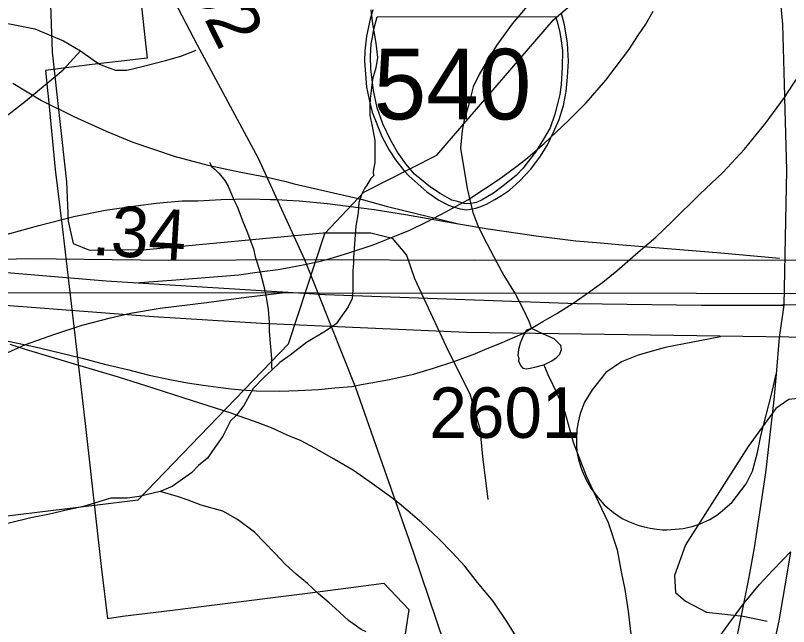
# Model space of a CAD drawing. Extents: x 2169602 to 2449496, y 721995 to 810662.
# Drawn here: x 2387770 to 2389685, y 798519 to 800033 of the extents above; entities that cross this region are included whole.
import ezdxf

# ---------------------------------------------------------------- set-up
doc = ezdxf.new("R2010")
doc.units = 0
doc.layers.add('Default', color=7, linetype='Continuous')

msp = doc.modelspace()

# ---------------------------------------------------------------- linework, layer by layer
at = {"layer": 'Default'}
for points in [[(2387480.1, 801917.5), (2387516.2, 801868.3), (2387556, 801747.9), (2387641.8, 801468.3), (2387761.6, 801071.5), (2387861, 800727), (2387914.9, 800579.3), (2388020.5, 800342.7), (2388219.9, 799960.5), (2388371.1, 799679.8), (2388485.8, 799428.9)], [(2389486.1, 801124.5), (2389522.7, 800969.7), (2389569.9, 800753.7), (2389596.1, 800625.4), (2389614.4, 800496), (2389638, 800341.5), (2389669.4, 800011.6), (2389674.7, 799833.5)], [(2388058.7, 800264.8), (2388096, 799927.2), (2387959.5, 799911.8), (2387844, 799896.7), (2387850, 799840.4), (2387850.7, 799833.2), (2387867.7, 799651.2), (2387885, 799509.9), (2387937, 799063.9), (2387943, 799014.9), (2387981.5, 798667.4), (2387997.2, 798538.9), (2388035, 798544), (2388158.5, 798559.2), (2388242.7, 798570.1), (2388499.5, 798602.2), (2388681.7, 798626.6), (2388744, 798561.1), (2388699.2, 798264.6)], [(2388058.7, 800264.8), (2388096, 799927.2), (2387959.5, 799911.8), (2387844, 799896.7), (2387850, 799840.4), (2387850.7, 799833.2), (2387867.7, 799651.2), (2387885, 799509.9), (2387937, 799063.9), (2387943, 799014.9), (2387981.5, 798667.4), (2387997.2, 798538.9), (2388035, 798544), (2388158.5, 798559.2), (2388242.7, 798570.1), (2388499.5, 798602.2), (2388681.7, 798626.6), (2388744, 798561.1), (2388699.2, 798264.6)], [(2387841.7, 800246.3), (2387854, 800130.9), (2387860.6, 799942.5), (2387896.1, 799621), (2387900.5, 799523.4), (2387912.7, 799468), (2387952.6, 799451.4), (2388093.3, 799453.6), (2388532.1, 799494.6), (2388649.5, 799494.6), (2388702.7, 799481.3), (2388738.1, 799439.2), (2388758.1, 799381.5), (2388842.3, 799200.8), (2388895.5, 799095.5), (2388919.9, 799009.1), (2388926.5, 798940.3), (2388939.8, 798833.9)], [(2388632.4, 799595.7), (2388813.3, 799687.2), (2389102.2, 800022.5), (2389318.1, 800208.3)], [(2389180.1, 800169.5), (2389142.1, 800141.6), (2389114.2, 800121.5), (2389076.1, 800091.1), (2389046.6, 800067.2), (2389000.4, 800012.9), (2388960.9, 799958.9), (2388941.2, 799926.6), (2388919, 799888.5), (2388903, 799856.5), (2388891.5, 799810.4), (2388881.3, 799774.6), (2388875.8, 799748.6), (2388872.3, 799704.6), (2388888.3, 799604.4), (2388902.6, 799544.6), (2388914.7, 799512.8), (2388930.9, 799480.7), (2388960.9, 799423), (2388979.5, 799389), (2389007.6, 799343.4), (2389027.5, 799305.5), (2389041.6, 799275.3), (2389047.6, 799257.4)], [(2388066.6, 799370.8), (2388167, 799378.5), (2388322.7, 799390.9), (2388374.3, 799397.6), (2388420.4, 799403.4), (2388452, 799409.1), (2388486.5, 799416.4), (2388528.9, 799425.4), (2388557.7, 799433.3), (2388593.3, 799444.1), (2388655.9, 799464.9), (2388713.6, 799487.6), (2388748.5, 799502), (2388790.2, 799522.5), (2388835.8, 799546.6), (2388890.4, 799576.3), (2388931.2, 799603.3), (2388967.9, 799627.4), (2389008, 799657.2), (2389032.9, 799676.5), (2389079.4, 799715.9), (2389139, 799771.9), (2389183.1, 799817.2), (2389232, 799873.2), (2389255.5, 799903.2), (2389289, 799947.9), (2389313.2, 799985.1), (2389331.1, 800011.5), (2389349.5, 800043.7)], [(2388654.7, 800047.4), (2388647.9, 800024.5), (2388639.5, 799982.5), (2388635.2, 799946), (2388634.4, 799920.1), (2388639.2, 799855.6), (2388646.2, 799821.3), (2388653.4, 799793.5), (2388677.3, 799733.4), (2388695.3, 799699.8), (2388710.7, 799675.7), (2388732.2, 799648.5), (2388743.9, 799635.5), (2388788.7, 799596.4), (2388818.7, 799575.9), (2388842.6, 799563), (2388853.8, 799558.7), (2388871.4, 799553.8), (2388887.6, 799552), (2388897, 799552.9), (2388909.8, 799555.4), (2388922.2, 799559.5), (2388936.3, 799565.7), (2388957.1, 799577.2), (2388973.8, 799587.1), (2388993.2, 799600.1), (2389019.3, 799623.8), (2389045.4, 799651.2), (2389068.3, 799682.2), (2389086.6, 799711.2), (2389102.7, 799744.4), (2389116.1, 799775.3), (2389126.8, 799810.6), (2389133.8, 799844.9), (2389137.4, 799880.6), (2389139.8, 799920.1), (2389137.1, 799964.7), (2389129.4, 800010.2), (2389122.1, 800038.6)], [(2388649.5, 800047.2), (2388654, 800012.8), (2388662.2, 799964.9), (2388666.3, 799929), (2388662.4, 799903.2), (2388654.4, 799875.2), (2388650.5, 799847), (2388648.4, 799827), (2388647, 799813.1), (2388647.2, 799800.9), (2388647, 799785.1), (2388653.4, 799759), (2388659.7, 799723.1), (2388659.7, 799695.1), (2388659.7, 799669.2), (2388656, 799647), (2388656, 799642.9), (2388657.7, 799637)], [(2387445.4, 799651.9), (2387417.8, 799670.5), (2387398.2, 799688.9), (2387382.7, 799709.2), (2387375, 799723.4), (2387356.1, 799777.7), (2387346.9, 799815.9), (2387334.4, 799886.2), (2387333.4, 799936.2), (2387333.8, 799956.2), (2387346.1, 799973.9), (2387382.5, 799995.2), (2387428.7, 800012.3), (2387499, 800030.8), (2387554.9, 800031.7), (2387608.7, 800028.6), (2387704.3, 800022.6), (2387817.6, 800000.3), (2387853.3, 799985.6), (2387888.9, 799970.8), (2387930.3, 799946)], [(2389674.8, 799829.7), (2389695.7, 799862.8), (2389711.9, 799886.2), (2389726.4, 799911.3), (2389741.4, 799937.5), (2389755.4, 799964.8), (2389762.5, 799979.3)], [(2387641.8, 799695.9), (2387682.5, 799735.1), (2387704.8, 799752.6), (2387794, 799820.8), (2387887.4, 799898.9), (2387930.3, 799946)], [(2387930.3, 799946), (2387961.8, 799923.4), (2387977.5, 799913), (2388003.2, 799902.5), (2388017.1, 799898.2), (2388029.1, 799898), (2388045.1, 799897.6), (2388083.2, 799906.9), (2388141.3, 799921.7), (2388179.5, 799932.9), (2388217.2, 799947.4)], [(2387763.2, 799865.5), (2387834.3, 799822.9), (2387914.4, 799782.9), (2387994.5, 799746.7), (2388060.4, 799719.6), (2388162.5, 799684.8), (2388246.4, 799662.1), (2388327.5, 799645), (2388392.7, 799632.6)], [(2389151.3, 799320.1), (2389183.3, 799342.7), (2389224.5, 799372.6), (2389259.6, 799400.3), (2389312.5, 799447), (2389355.5, 799484.2), (2389396.4, 799522.8), (2389465.3, 799590.5), (2389521.6, 799644.4), (2389575.4, 799701.6), (2389629.6, 799767.9), (2389674.8, 799829.7)], [(2389674.8, 799829.7), (2389679.9, 799650.2), (2389672.9, 799315.6)], [(2389674.5, 799838.6), (2389674.8, 799829.7)], [(2388250, 799669.9), (2388256.2, 799658), (2388264, 799652), (2388274.2, 799641.9), (2388288.4, 799624), (2388296.2, 799610.2), (2388310.5, 799576.4), (2388318.5, 799560.2), (2388332.7, 799522.3), (2388342.7, 799498.5), (2388359.1, 799454.7), (2388363, 799435), (2388375.5, 799397), (2388384.9, 799362.7), (2388391.5, 799330.5), (2388395.4, 799304.8), (2388397.7, 799272.8), (2388397.9, 799250.8), (2388399.9, 799230.6), (2388402.2, 799202.7), (2388404.2, 799182.5), (2388404.2, 799164.7), (2388404.4, 799154.5)], [(2382211.2, 799653), (2383616.4, 799527.7), (2384066.4, 799492.2), (2384576.2, 799439.6), (2385095.5, 799400.2), (2385362.9, 799383.7), (2385870.7, 799361), (2386840.4, 799347.1), (2388518.9, 799345.9)], [(2388657.7, 799637), (2388650.1, 799629.3), (2388640, 799613), (2388634.1, 799604.9)], [(2385171.5, 799625), (2386720.5, 799488.1), (2386833.2, 799477.1), (2387540.6, 799413.4), (2387994.5, 799375.3), (2388537.1, 799341.5), (2389161.4, 799319.7), (2389469.2, 799314.9), (2389672.9, 799315.6)], [(2388392.7, 799632.6), (2388436, 799622.5), (2388460.3, 799615.9), (2388625.7, 799577.7), (2388688.1, 799560.4), (2388866.7, 799517)], [(2388634.1, 799604.9), (2388627.9, 799590.9), (2388620.1, 799569.7), (2388618.5, 799544.4), (2388612.5, 799511.2), (2388608.4, 799456.3), (2388607, 799432.6), (2388607, 799420), (2388605.2, 799400.8), (2388605.2, 799380.1), (2388605.4, 799353.7), (2388603.3, 799331.7), (2388593.7, 799311.3), (2388563.7, 799269.1), (2388537.7, 799251.2), (2388490.1, 799223.1), (2388449.9, 799191), (2388424.3, 799173), (2388404.4, 799154.5)], [(2386095.3, 795740.6), (2386129.2, 795782.6), (2386136.3, 795959.6), (2386341.2, 796769), (2386588.3, 797328.1), (2386903.2, 797653), (2386961.3, 797753.5), (2387169.2, 797962.5), (2387235.2, 798144.9), (2387258.2, 798570.9), (2387374.2, 798680), (2387640.2, 798779.6), (2388073.3, 798833), (2388446.2, 799219.1), (2388536.3, 799492.8), (2388632.4, 799595.7)], [(2387582.8, 799431.5), (2387637, 799454.6), (2387731.1, 799486.4), (2387827.5, 799513), (2387914.3, 799535.4), (2387991.8, 799551.1), (2388067.8, 799561.2), (2388118.1, 799568.4), (2388182.7, 799574.1), (2388221.4, 799574.1), (2388279.4, 799577), (2388349, 799578.5), (2388401.1, 799577), (2388418.1, 799577)], [(2388418.1, 799577), (2388442.1, 799575.8), (2388472.5, 799573.7), (2388542.9, 799567.5), (2388561.7, 799564.7), (2388658, 799552.3), (2388735.5, 799539.9), (2388866.7, 799517)], [(2385227, 799540.2), (2386632.2, 799414.9), (2387082.3, 799379.3), (2387592, 799326.8), (2388111.3, 799287.4), (2388378.7, 799270.9), (2388886.5, 799248.2), (2389856.2, 799234.3), (2391534.7, 799233)], [(2388866.7, 799517), (2388940.7, 799504.8), (2389064.9, 799486.2), (2389157.9, 799474.8), (2389218.9, 799469.7), (2389273.7, 799464.5), (2389516.9, 799444.9), (2389662.6, 799431.5)], [(2386745.4, 799430.9), (2387582.8, 799431.5), (2387619.5, 799432.1), (2387741.2, 799429.6), (2387801, 799431.3), (2388147.5, 799426.5), (2388485.8, 799428.9)], [(2388485.8, 799428.9), (2388907.6, 799426.8), (2391428, 799428.5), (2391747.2, 799418.3), (2391908.5, 799407.4), (2392123.6, 799386.6), (2392339.3, 799355.4)], [(2388485.8, 799428.9), (2388518.9, 799345.9)], [(2388518.9, 799345.9), (2390392.7, 799344.5), (2390915.3, 799351.2), (2391147.5, 799347.5), (2391397.7, 799346.6), (2391504.7, 799346.7), (2391681, 799343.3), (2391852.6, 799330.5), (2392075.5, 799306.6), (2392258.8, 799284.4), (2392395.4, 799262)], [(2386750.8, 798377.2), (2386792.9, 798431.5), (2386855.5, 798501.2), (2386901.6, 798547.3), (2387003, 798642.3), (2387127.1, 798749.6), (2387261.8, 798864), (2387397.7, 798977.6), (2387467.3, 799031.5), (2387501.6, 799057.9), (2387553.3, 799091.6), (2387616.6, 799129.9), (2387678.8, 799163.4), (2387734.4, 799190.2), (2387794, 799217.9), (2387866.8, 799243.8), (2387934.8, 799265.8), (2388004.8, 799284), (2388054.6, 799295.5), (2388127.6, 799307.9), (2388242.8, 799322.3), (2388341, 799334.8), (2388430, 799345.9)], [(2388518.9, 799345.9), (2388612.3, 799111.2), (2388755.1, 798703.9), (2388850.3, 798420.1), (2388917.3, 798187.7), (2389001.5, 797937.4), (2389116.1, 797621.2), (2389137.6, 797520.7)], [(2389026.8, 799245), (2389076, 799274.5), (2389110.5, 799294.9), (2389151.3, 799320.1)], [(2389151.3, 799320.1), (2389161.4, 799319.7)], [(2389672.9, 799315.6), (2389661.8, 799235), (2389654, 799144.1)], [(2389669, 799316.3), (2389761.3, 799318)], [(2389669, 799316.3), (2389669, 799315.1)], [(2389047.6, 799257.4), (2389035.9, 799253.5), (2389027.9, 799241.3), (2389019.9, 799221.4), (2389016, 799205.4), (2389014.2, 799191.1), (2389016.2, 799183.1), (2389016, 799177.4), (2389020.3, 799165.4), (2389026.3, 799159.2), (2389036.5, 799157.3), (2389056.4, 799161.6), (2389078.1, 799167.6)], [(2389078.1, 799167.6), (2389098, 799177.6), (2389110.1, 799185.9), (2389118.1, 799193.6), (2389121.8, 799205.6), (2389120.2, 799215.6), (2389104.2, 799231.8), (2389077.7, 799243.6), (2389059.9, 799251.5), (2389047.6, 799257.4)], [(2387707.7, 799235.4), (2387818, 799212.3), (2387876.9, 799197.6), (2387934.9, 799183.8), (2387990.1, 799169.1), (2388047.1, 799155.6), (2388082.1, 799146.6), (2388100.7, 799142.1), (2388156.3, 799130.6), (2388195.7, 799122.6), (2388234.2, 799116.9), (2388272, 799112.1), (2388304.2, 799108.1), (2388329.1, 799105.7), (2388365.6, 799103.2), (2388423.8, 799102.3), (2388469.5, 799104.1), (2388520.6, 799105.9), (2388560.9, 799110.4), (2388602.9, 799113.9), (2388627.1, 799118.4), (2388695.9, 799130.9), (2388755.7, 799144.4), (2388805.2, 799159.1), (2388855.9, 799175.9), (2388903.3, 799192.8), (2388938.2, 799207.5), (2388969.7, 799219.9), (2389026.8, 799245)], [(2389516, 799236.8), (2389379, 799210.3), (2389312.5, 799191.7), (2389270.7, 799174.7), (2389232, 799148.4), (2389198, 799105.1), (2389179.2, 799074.6), (2389168.7, 799046.6), (2389163.2, 799025.1), (2389160.4, 799007.2), (2389159.5, 798984.8), (2389159.5, 798963.3), (2389160.9, 798947.7), (2389164.5, 798932.1), (2389172.5, 798905.9), (2389183.2, 798882.4), (2389195, 798862), (2389212.7, 798837.4), (2389228.3, 798820.2), (2389251.3, 798801.5), (2389272.8, 798786.5), (2389286.2, 798779.5), (2389311, 798769.8), (2389326.6, 798765.5), (2389341.7, 798762.4), (2389358, 798759.9), (2389372.1, 798758.7), (2389383.2, 798758.4), (2389394.2, 798759), (2389424, 798762.1), (2389446.3, 798766.9), (2389465.7, 798773.5), (2389489.8, 798784.4), (2389509.1, 798796.5), (2389527.2, 798810.9), (2389544.8, 798827.2), (2389579.7, 798872.1), (2389595.2, 798904.1), (2389607.9, 798949.7), (2389615.6, 798991.3), (2389642.8, 799094), (2389654, 799144.1)], [(2390747.6, 799230.9), (2390676.6, 799246.5), (2390599.1, 799250.9), (2390499.3, 799250.9), (2390428.9, 799248.5), (2390325.5, 799231.3), (2390126.1, 799174.7), (2390000.6, 799150), (2389887.4, 799120.5), (2389788.9, 799093.4), (2389685.5, 799081.1), (2389653.5, 799058.9), (2389584.6, 798965.3), (2389429.5, 798721.6), (2389402.5, 798645.2), (2389404.9, 798603.4), (2389429.5, 798581.2), (2389481.2, 798554.1), (2389572.3, 798544.3), (2389631.4, 798531.9)], [(2389010.2, 798494.1), (2388988.3, 798528.3), (2388952.9, 798582), (2388914.4, 798627.5), (2388882.7, 798668.7), (2388851.7, 798702.1), (2388818.4, 798736.3), (2388776, 798776.1), (2388747.5, 798800.5), (2388719.9, 798823.3), (2388698.7, 798840.4), (2388654.3, 798872.4), (2388606.7, 798905.2), (2388559.1, 798933.8), (2388511.5, 798960.6), (2388476.9, 798978.7), (2388442.3, 798993.4), (2388403.4, 799011.3), (2388364, 799026.2), (2388321.6, 799041.1), (2388303.7, 799047.7), (2388187.2, 799084.5), (2388110.4, 799109.6), (2388024.4, 799136.9), (2387923.7, 799166.6), (2387794.6, 799205.1), (2387756.7, 799217.5)], [(2389078.1, 799167.6), (2389088.2, 799143.7), (2389112.6, 799093.8), (2389130.8, 799049.7), (2389151.1, 798976.1), (2389183.1, 798892.1), (2389213.3, 798828.3), (2389237.9, 798776.3), (2389260, 798708.5), (2389270.3, 798654.6), (2389278.7, 798610.4), (2389287.1, 798556.7), (2389293.2, 798506.8), (2389305.3, 798436.8), (2389313.5, 798369), (2389320.3, 798299), (2389334.2, 798204.8), (2389346.3, 798145), (2389352.9, 798097), (2389361.1, 798031.2), (2389369.3, 797971.2), (2389373.2, 797963.3)], [(2388404.4, 799154.5), (2388386, 799136.6), (2388358.5, 799108.7), (2388334.9, 799066.5), (2388316.9, 799042.4), (2388302.5, 799028.4), (2388283, 798990.3), (2388263.1, 798962.1), (2388245.1, 798936), (2388222.9, 798917.9), (2388205.5, 798899.8), (2388183.2, 798883.7), (2388157.7, 798865.7), (2388127.6, 798853.6)], [(2389654, 799144.1), (2389648.5, 799080.8), (2389627.2, 798900), (2389599.7, 798714), (2389586.6, 798640.7), (2389573.1, 798574.9)], [(2388127.6, 798853.6), (2388075.9, 798841.1), (2388046, 798837.2), (2388006, 798837.1), (2387937.9, 798816.6), (2387892, 798806.5), (2387858, 798798.3), (2387807.9, 798788.4), (2387750.3, 798774), (2387712.4, 798765.9), (2387636.3, 798741.3), (2387584, 798741.1), (2387544.4, 798745.1), (2387506.5, 798735), (2387470.2, 798718.6), (2387440.3, 798704.5), (2387406.8, 798684.4), (2387372.8, 798654.2), (2387347, 798632.2), (2387330.8, 798616), (2387326.9, 798608), (2387319.1, 798596.3), (2387309.2, 798566.1), (2387305.1, 798546)], [(2388638.4, 798505.4), (2388626.1, 798511.3), (2388594.5, 798533.5), (2388562.5, 798563.5), (2388546.7, 798577.7), (2388520.5, 798599.5), (2388492.6, 798625.2), (2388464.7, 798648.9), (2388438.5, 798672.7), (2388412, 798700.7), (2388386.2, 798726.9), (2388362, 798752.9), (2388319.7, 798784.4), (2388283.6, 798804.5), (2388229.5, 798819.9), (2388197.5, 798832.1), (2388173.7, 798839.8), (2388127.6, 798853.6)], [(2389689.4, 798703.6), (2389680.7, 798648.2), (2389660.9, 798532.5), (2389615.7, 798326.4), (2389550.7, 798063.8), (2389466, 797771.9), (2389389.7, 797506.6), (2389380.8, 797474.1)], [(2389573.1, 798574.9), (2389612.8, 798623.1), (2389644.7, 798657.7), (2389670.8, 798684.3), (2389689.4, 798703.6)], [(2389573.1, 798574.9), (2389535.5, 798390.5), (2389472.6, 798154.8), (2389399.2, 797861.4), (2389310.1, 797568.1), (2389213.9, 797220.4), (2389086.2, 796756.6)], [(2389212.7, 797710.8), (2389232.1, 797814.6), (2389240.9, 797853.3), (2389249.5, 797891.6), (2389261.3, 797948.8), (2389269.7, 797979.9), (2389296.4, 798066.5), (2389318.3, 798130.4), (2389336.4, 798173.3), (2389347.8, 798200), (2389365.8, 798236.8), (2389382.5, 798271.4), (2389419, 798342.7), (2389450.2, 798397.6), (2389473.9, 798438.5), (2389502.6, 798479.4), (2389555.1, 798549.9), (2389573.1, 798574.9)]]:
    msp.add_lwpolyline(points, dxfattribs=at)
msp.add_lwpolyline([(2389107.1, 800030.5), (2389111.7, 800018.3), (2389118.1, 799991.2), (2389121.4, 799970.4), (2389124.8, 799946.4), (2389123.6, 799905.3), (2389121.6, 799862.7), (2389117.7, 799837.5), (2389112.5, 799814.5), (2389105.3, 799789.1), (2389093.8, 799755.2), (2389077.9, 799726.6), (2389058, 799694.8), (2389036.5, 799666.9), (2389027.2, 799655.3), (2389009.5, 799636.7), (2388977.3, 799610.8), (2388953.8, 799593.2), (2388925.6, 799576.6), (2388911.3, 799570.2), (2388894.6, 799566.7), (2388880.9, 799567.7), (2388864.3, 799572.1), (2388850.8, 799575.8), (2388821.4, 799591.7), (2388797.5, 799607.6), (2388757.8, 799640.2), (2388736.3, 799665.4), (2388716.3, 799694.7), (2388698.4, 799724.8), (2388679.3, 799764.5), (2388665.9, 799804.4), (2388656.1, 799847.5), (2388649.5, 799900.1), (2388648.7, 799932.2), (2388650.7, 799963), (2388653.6, 799979.2), (2388657.5, 799999.3), (2388665.4, 800030.2)], close=True, dxfattribs=at)

# ---------------------------------------------------------------- texts
for s, rotation, p in [('.92', 296.1854, (2388174.4, 800151.1)), ('.34', 356.4375, (2387957.2, 799440.2))]:
    msp.add_text(s, height=125, rotation=rotation, dxfattribs=at).set_placement(p)
for s, height, p in [('540', 175, (2388656.9, 799775.8)), ('2601', 125, (2388794.9, 798986.4))]:
    msp.add_text(s, height=height, dxfattribs=at).set_placement(p)

doc.saveas('drawing.dxf')
